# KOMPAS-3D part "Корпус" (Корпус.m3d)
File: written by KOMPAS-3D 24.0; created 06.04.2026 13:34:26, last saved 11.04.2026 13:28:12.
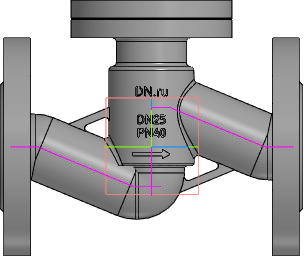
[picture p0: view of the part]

Document properties: Автор: R2D2; Полное имя файла: E:\Работа\Зайцев\VSO3131M-F-S Клапан запорный DN.ru Ду15-100 Ру40\DN25\исходные материалы\Корпус.m3d

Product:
- Body: Труба / Нестандартная труба / L = 79.1 мм  | qty 1
    Материал: Нестандартная труба (density 7856 kg/m3)
    Масса: 4.563903
    Раздел спецификации: Детали
    Примечание: 0,6 кг
    additional columns: Pipeline; 0.035; 0; 0; 0.002; 0.07905; true; 0.04
- Body: Труба / Нестандартная труба / L = 96.8 мм  | qty 1
    Материал: Нестандартная труба (density 7856 kg/m3)
    Масса: 4.563903
    Раздел спецификации: Детали
    Примечание: 0,73 кг
    additional columns: Pipeline; 0.035; 0; 0; 0.002; 0.09675; true; 0.04
- Body: Тело 4  | qty 1
    Материал: Нестандартная труба (density 7856 kg/m3)
    Масса: 4.563903
- Body: Тело 5  | qty 1
    Материал: Нестандартная труба (density 7856 kg/m3)
    Масса: 4.563903
- Body: Тело 8  | qty 1
    Материал: Нестандартная труба (density 7856 kg/m3)
    Масса: 4.563903
- Body: Тело 9  | qty 1
    Материал: Нестандартная труба (density 7856 kg/m3)
    Масса: 4.563903
- Part/product: Корпус
    Масса: 6.9

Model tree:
1. Труба
2. Труба:1  (labels: {F703FF30-5BE6-4673-A7F1-8EDA1BE1E2D1}; SHAPEOBJECT3D_ATTR_BUTT; SHAPEOBJECT3D_ATTR_VALID; SHAPEOBJECT3D_ATTR_BUTT_AREA)
     PIPE_R = 7
3. Труба:2  (labels: {F703FF30-5BE6-4673-A7F1-8EDA1BE1E2D1}; SHAPEOBJECT3D_ATTR_BUTT; SHAPEOBJECT3D_ATTR_VALID; SHAPEOBJECT3D_ATTR_BUTT_AREA)
     PIPE_R = 7
4. Колонна
5. Элемент выдавливания:1
     Смещение 1 = -1; Смещение 2 = -5
6. Скругление:17  (with: Ребро.Элемент выдавливания:1)
     Радиус = 1
7. Скругление:18  (with: Ребро.Элемент выдавливания:1)
8. Скругление:24  (with: Ребро.Элемент выдавливания:1)
     Радиус = 1.5
9. Элемент выдавливания:2
     Расстояние 1 = 6
10. Скругление:19  (with: Ребро.Элемент выдавливания:2)
     Радиус = 2
11. Эскиз:4  (with: Грань.Элемент выдавливания:1)
12. Элемент выдавливания:3
     Расстояние 1 = 15
13. Скругление:21  (with: Ребро.Элемент выдавливания:3)
14. ОТЛИВКА
15. Скругление:6  (with: Грань.Элемент выдавливания:1)
     Радиус = 2
16. Элемент выдавливания:6  (with: Грань.Элемент выдавливания:1)
     Смещение 1 = 4
17. ЛЕЙБЛ
18. Элемент выдавливания:7  (with: Грань.Элемент выдавливания:1)
     Расстояние 1 = 23.4987; Смещение 1 = 1
19. Фланец верх  (with: Ребро.Элемент выдавливания:3)
20. Элемент вращения:2
     Угол 1 = 360
21. Эскиз:12  (with: Грань.Элемент вращения:2)
22. Элемент выдавливания:9  (with: Грань.Элемент вращения:2)
     Расстояние 2 = 20
23. Массив по концентрической сетке:1  (with: Элемент выдавливания:9, Эскиз:12, Грань.Элемент вращения:2)  (4 pattern instances)
     Шаг 2 = 360
24. Фланец
25. Элемент вращения:1
     Угол 1 = 360
26. Эскиз:10  (with: Грань.Элемент вращения:1)
27. Элемент выдавливания:8
28. Массив по концентрической сетке:2  (with: Элемент выдавливания:8, Эскиз:10, Грань.Элемент вращения:1)  (4 pattern instances)
     Шаг 2 = 360
29. Зеркальный массив:1
30. Экземпляр ( 1 )
31. Экземпляр ( 2 )  (with: Элемент вращения:1, Массив по концентрической сетке:2, Экземпляр ( 1 ), Элемент выдавливания:8)
32. Экземпляр ( 3 )  (with: Элемент выдавливания:8)
33. Экземпляр ( 4 )  (with: Элемент выдавливания:8)
34. Скругление:25  (with: Ребро.Элемент вращения:2)
     Радиус = 2

Expressions: DS/2+3; D1/2; DN/2; D/2; DS-v977*4; LL/2; D1-v1234*2
Referenced files in C:\Program Files\ASCON\KOMPAS-3D v24\Libs\Pipeline\: StylesTemplate.a3d, TemplateHPH, InsulationStylesTemplate.a3d, Insulation
Referenced files in C:\Program Files\ASCON\KOMPAS-3D v24\Templates\: Констр. чертеж А3 гориз. перв. лист.cdt
Referenced files in E:\Работа\Зайцев\VSO3131M-F-S Клапан запорный DN.ru Ду15-100 Ру40\DN20\исходные материалы\: 
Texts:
  Отводы ГОСТ 17375-2001
  Констр. чертеж А3 гориз. перв. лист.cdt
  GOST 26.020 Pr3
  var3D
  GOST 2.304 type A
  смещение колонны вниз
  LL-10
  DN+10
  Труба / Нестандартная труба / L = %s мм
